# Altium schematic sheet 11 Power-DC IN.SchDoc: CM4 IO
size 420 x 297 mm; Page Create Date: March  8, 1995; Page Number: 11; Page Size: A3; Comment: radxa_1010; Page Count: 19; RevCode: V1.10; Doc: 11 Power-DC IN; DsnPath: D:\WMS\黄工\[RC126]CM4_IO_V1.10\[RC126]_V1.10\CM4 IO_V1.10.DSN; SchematicName: CM4 IO V1.10; PageName: 11 Power-DC IN; PageSize: A3; TopSchematic: True
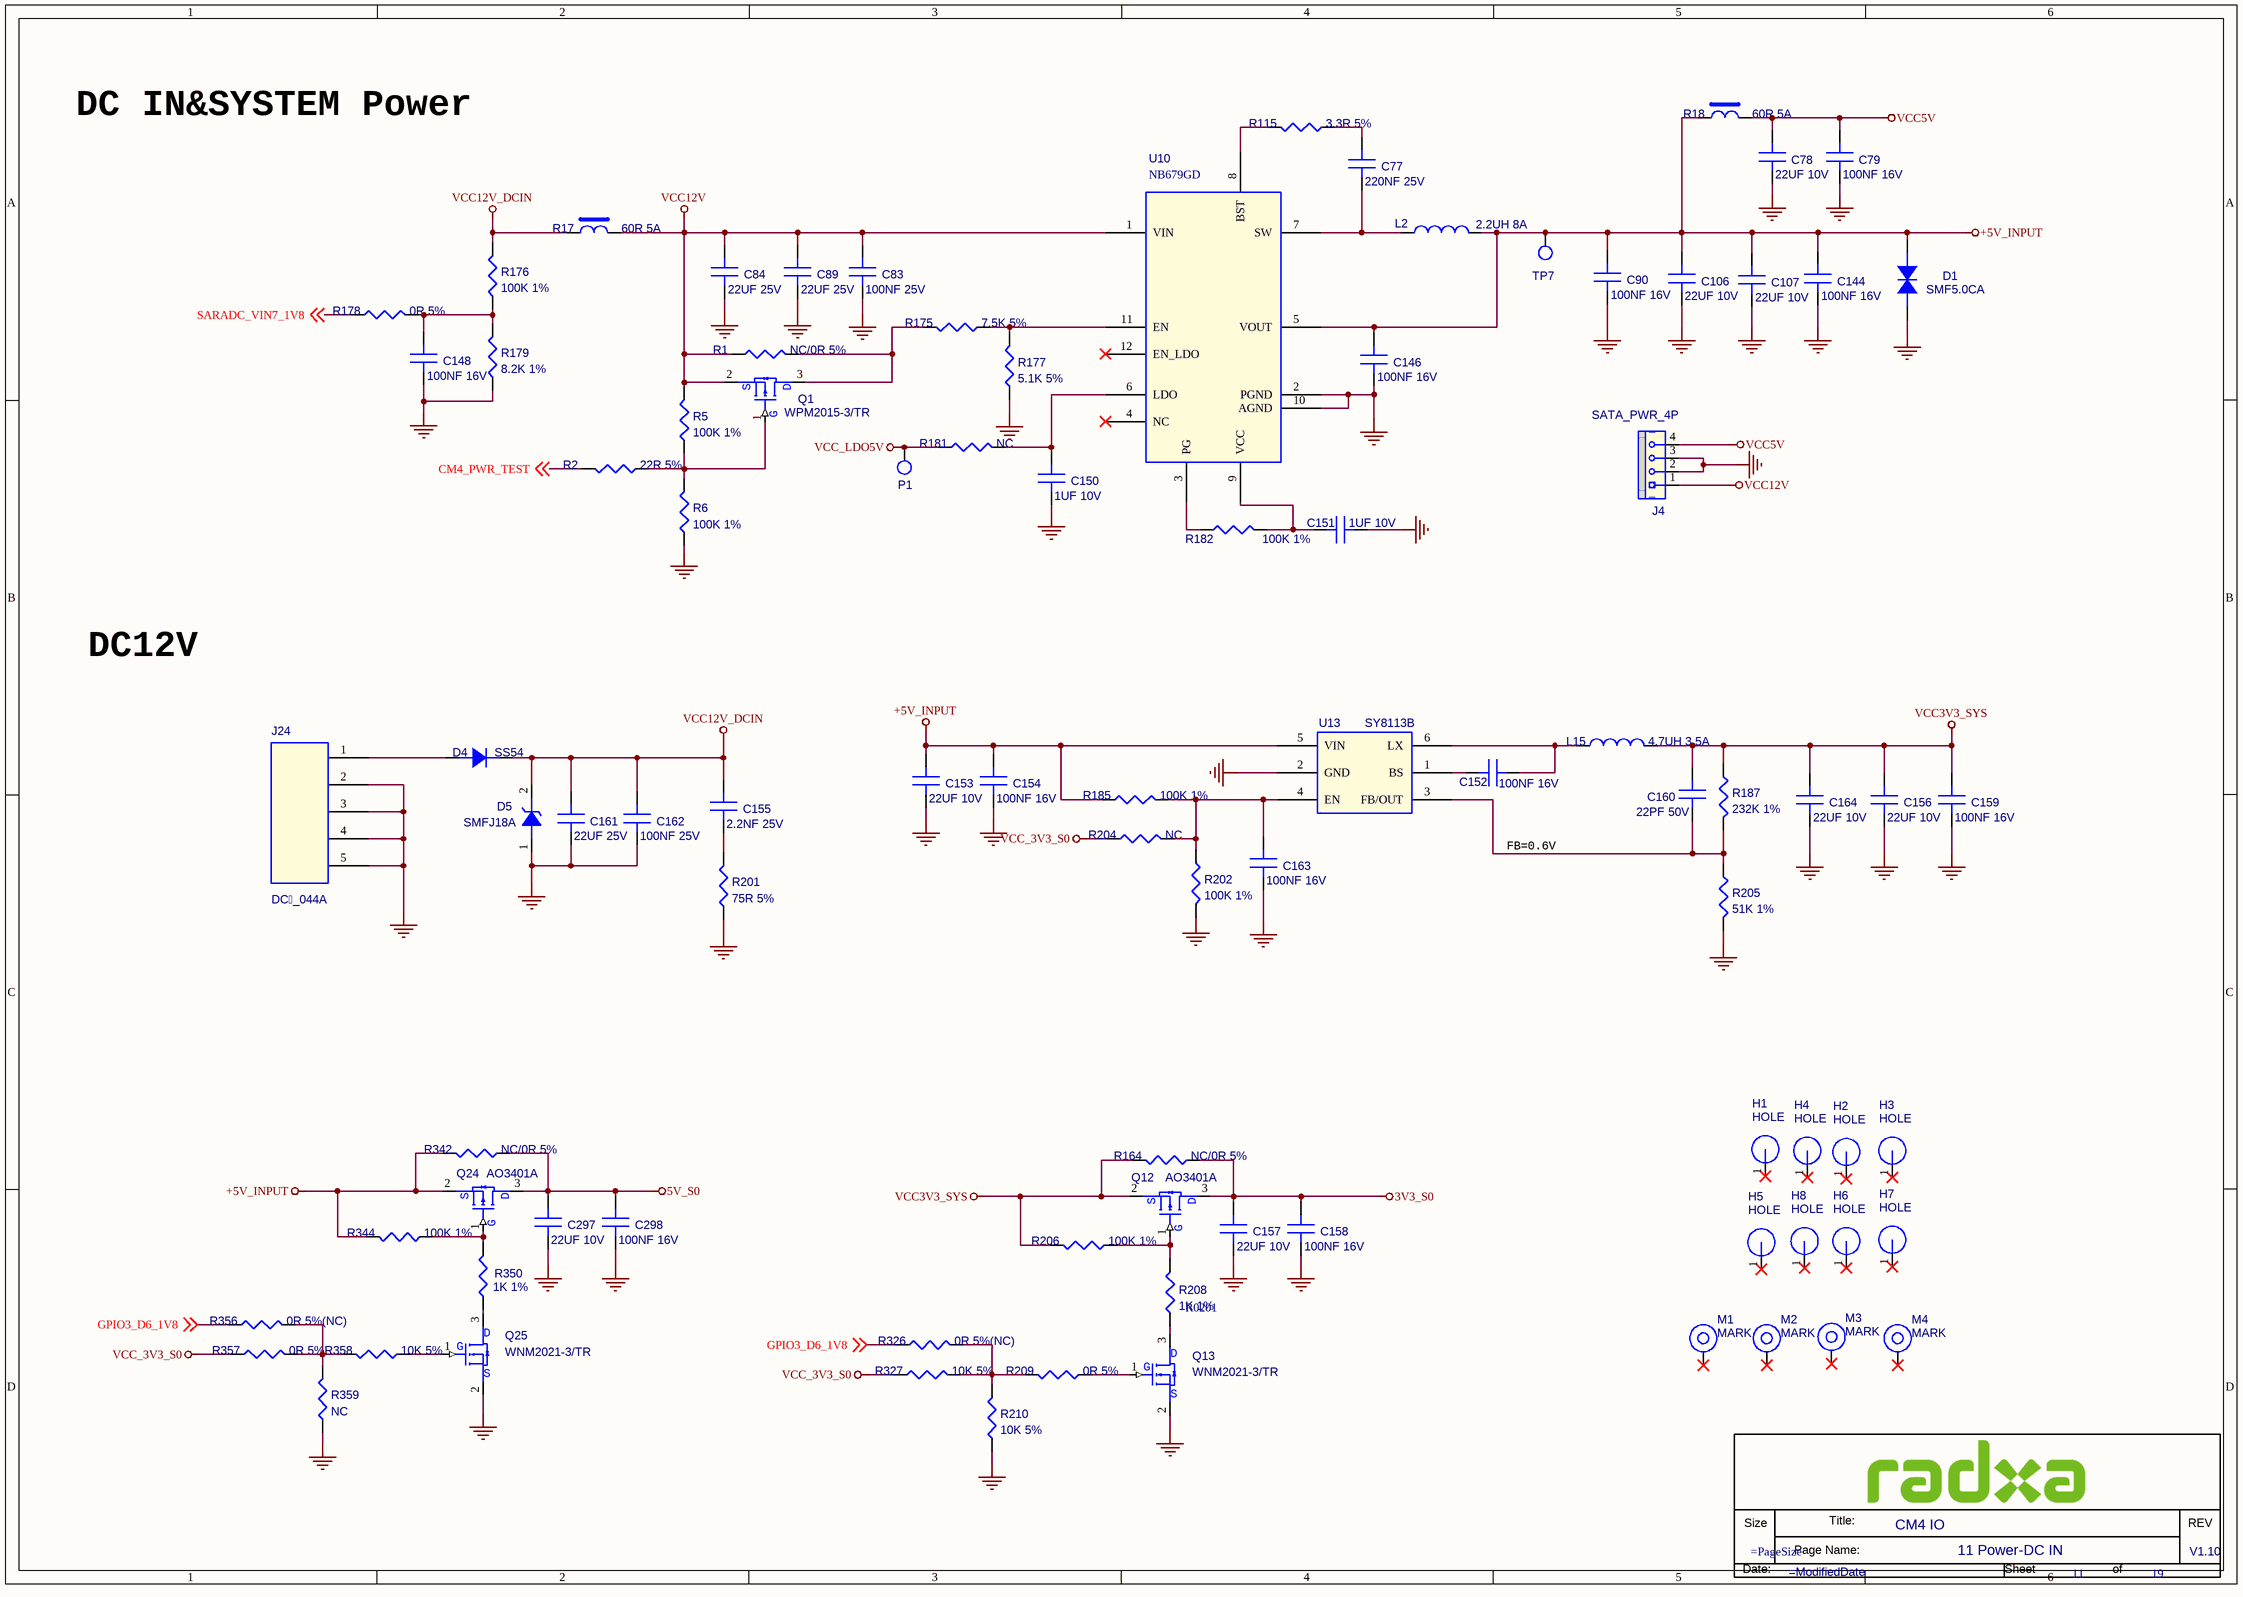
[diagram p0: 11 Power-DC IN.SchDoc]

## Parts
*  Doc: 11 Power-DC IN  RevCode: V1.10  Title: CM4 IO  Page Number: 11  Page Count: 19  (hidden comment: radxa_1010)  (graphical)
C77  220NF 25V  [C0201]
C78  22UF 10V  [C0603]
C79  100NF 16V  [C0201]
C83  100NF 25V  [C0201]
C84  22UF 25V  [C0805]
C89  22UF 25V  [C0805]
C90  100NF 16V  [C0201]
C106  22UF 10V  [C0603]
C107  22UF 10V  [C0603]
C144  100NF 16V  [C0201]
C146  100NF 16V  [C0201]
C148  100NF 16V  [C0201]
C150  1UF 10V  [C0201]
C151  1UF 10V  [C0201]
C152  100NF 16V  [C0201]
C153  22UF 10V  [C0603]
C154  100NF 16V  [C0201]
C155  2.2NF 25V  [C0201]
C156  22UF 10V  [C0603]
C157  22UF 10V  [C0603]
C158  100NF 16V  [C0201]
C159  100NF 16V  [C0201]
C160  22PF 50V  [C0201]
C161  22UF 25V  [C0805]
C162  100NF 25V  [C0201]
C163  100NF 16V  [C0201]
C164  22UF 10V  [C0603]
C297  22UF 10V  [C0603]
C298  100NF 16V  [C0201]
D1  SMF5.0CA  [SOD_123]
D4  SS54  [DO_214AC]
D5  SMFJ18A  [SOD_123]
H1  HOLE  [H3.8MM]
H2  HOLE  [H3.8MM]
H3  HOLE  [H3.8MM]
H4  HOLE  [H3.8MM]
H5  HOLE  [H3.8MM]
H6  HOLE  [H3.8MM]
H7  HOLE  [H3.8MM]
H8  HOLE  [H3.8MM]
J4  SATA_PWR_4P  [CON_TH1X4_2D54_SATA]
J24  DC_044A  [DC_TH5_12X10]
L2  2.2UH 8A  [L_6050]
L15  4.7UH 3.5A  [L_5020]
M1  MARK  [MARK]
M2  MARK  [MARK]
M3  MARK  [MARK]
M4  MARK  [MARK]
P1  TEST  [TEST]  (value not drawn)
Q1  WPM2015-3/TR  [SOT_23]
Q12  AO3401A  [SOT_23]
Q13  WNM2021-3/TR  [SOT_323]
Q24  AO3401A  [SOT_23]
Q25  WNM2021-3/TR  [SOT_323]
R1  NC/0R 5%  [R0402]
R2  22R 5%  [R0402]
R5  100K 1%  [R0402]
R6  100K 1%  [R0402]
R17  60R 5A  [FB1206]
R18  60R 5A  [FB1206]
R115  3.3R 5%  [R0402]
R164  NC/0R 5%  [R0402]
R175  7.5K 5%  [R0402]
R176  100K 1%  [R0402]
R177  5.1K 5%  [R0402]
R178  0R 5%  [R0402]
R179  8.2K 1%  [R0402]
R181  NC  [R0402]
R182  100K 1%  [R0402]
R185  100K 1%  [R0402]
R187  232K 1%  [R0402]
R201  75R 5%  [R0402]
R202  100K 1%  [R0402]
R204  NC  [R0402]
R205  51K 1%  [R0402]
R206  100K 1%  [R0402]
R208  1K 1%  PCB Footprint: R0201  [R0402]
R209  0R 5%  [R0402]
R210  10K 5%  [R0402]
R326  0R 5%(NC)  [R0402]
R327  10K 5%  [R0402]
R342  NC/0R 5%  [R0402]
R344  100K 1%  [R0402]
R350  1K 1%  [R0402]
R356  0R 5%(NC)  [R0402]
R357  0R 5%  [R0402]
R358  10K 5%  [R0402]
R359  NC  [R0402]
TP7  TP_0.7  [TEST]  (value not drawn)
U10  NB679GD  [QFN12_0D5_2]
U13  SY8113B  [SOT23_6]

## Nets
3V3_S0: C157.1(A) C158.1(A) Q12.3(D) R164.1
5V_S0: C297.1(A) C298.1(A) Q24.3(D) R342.1
+5V_INPUT: C90.1(A) C106.1(A) C107.1(A) C144.1(A) C146.1(A) C153.1(A) C154.1(A) D1.2(CATHODE) L2.2 Q24.2(S) R18.1 R185.1 R342.2 R344.2 TP7.1 U10.5(VOUT) U13.5(VIN)
GND: C78.2(B) C79.2(B) C83.2(B) C84.2(B) C89.2(B) C90.2(B) C106.2(B) C107.2(B) C144.2(B) C146.2(B) C148.2(B) C150.2(B) C151.2(B) C153.2(B) C154.2(B) C156.2(B) C157.2(B) C158.2(B) C159.2(B) C161.1(A) C162.2(B) C163.2(B) C164.2(B) C297.2(B) C298.2(B) D1.1(ANODE) D5.1(ANODE) J4.2 J4.3 J24.2 J24.3 J24.4 J24.5 Q13.2(S) Q25.2(S) R6.1 R177.1 R179.1 R201.1 R202.2 R205.2 R210.2 R359.2 U10.2(PGND) U10.10(AGND) U13.2(GND)
VCC3V3_SYS: C156.1(A) C159.1(A) C160.1(A) C164.1(A) L15.2 Q12.2(S) R164.2 R187.1 R206.2
VCC5V: C78.1(A) C79.1(A) J4.4 R18.2
VCC12V: C83.1(A) C84.1(A) C89.1(A) J4.1 Q1.2(S) R1.1 R5.2 R17.2 U10.1(VIN)
VCC12V_DCIN: C155.1(A) C161.2(B) C162.1(A) D4.2(K) D5.2(CATHODE) R17.1 R176.2
VCC_3V3_S0: R204.1 R327.1 R357.1
VCC_LDO5V: P1.1 R181.1
CM4_PWR_TEST: R2.1 ; off-sheet CM4_PWR_TEST
GPIO3_D6_1V8: R326.1 R356.1 ; off-sheet GPIO3_D6_1V8
SARADC_VIN7_1V8: R178.1 ; off-sheet SARADC_VIN7_1V8
NetC77_1: C77.1(A) R115.2
NetC77_2: C77.2(B) L2.1 U10.7(SW)
NetC148_1: C148.1(A) R176.1 R178.2 R179.2
NetC150_1: C150.1(A) R181.2 U10.6(LDO)
NetC151_1: C151.1(A) R182.2 U10.9(VCC)
NetC152_1: C152.1(A) U13.1(BS)
NetC152_2: C152.2(B) L15.1 U13.6(LX)
NetC155_2: C155.2(B) R201.2
NetC160_2: C160.2(B) R187.2 R205.1 U13.3(FB/OUT)
NetC163_1: C163.1(A) R185.2 R202.1 R204.2 U13.4(EN)
NetD4_1: D4.1(A) J24.1
NetQ1_1: Q1.1(G) R2.2 R5.1 R6.2
NetQ1_3: Q1.3(D) R1.2 R175.2
NetQ12_1: Q12.1(G) R206.1 R208.1
NetQ13_1: Q13.1(G) R209.1
NetQ13_3: Q13.3(D) R208.2
NetQ24_1: Q24.1(G) R344.1 R350.1
NetQ25_1: Q25.1(G) R358.1
NetQ25_3: Q25.3(D) R350.2
NetR115_1: R115.1 U10.8(BST)
NetR175_1: R175.1 R177.2 U10.11(EN)
NetR182_1: R182.1 U10.3(PG)
NetR209_2: R209.2 R210.1 R326.2 R327.2
NetR356_2: R356.2 R357.2 R358.2 R359.1

Not connected (* = marked no-connect by the designer): H1 1*; H2 1*; H3 1*; H4 1*; H5 1*; H6 1*; H7 1*; H8 1*; M1 1*; M2 1*; M3 1*; M4 1*; U10 4(NC)* 12(EN_LDO)*

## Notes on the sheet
- DC IN&SYSTEM Power
- DC12V
- FB=0.6V

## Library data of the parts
C77 = C: SMD  0201  220NF  25V  X5R  ±10%  ROHS; PARTS: 1; Part Reference: C77; Part Number: A1C01.00365; OriginalSymbolOrigin: (0,30); PKG_TYPE: CAP2-100-250; LEVEL: STD; PINSWAP: (A,B); Preferred: 6715f349cd0bc5
C78 = C: SMD  0603  22UF  10V  X5R  ±20%  ROHS; PARTS: 1; Part Reference: C78; Part Number: A1C01.00015; OriginalSymbolOrigin: (0,30); PKG_TYPE: CAP2-100-250; LEVEL: STD; PINSWAP: (A,B); Preferred: 6715f349cd0bc5
C79 = C: SMD  0201  100NF  16V  X5R  ±20%  ROHS; PARTS: 1; Part Reference: C79; Part Number: A1C01.00099; OriginalSymbolOrigin: (0,30); PKG_TYPE: CAP2-100-250; LEVEL: STD; PINSWAP: (A,B); Preferred: 6715f349cd0bc5
C83 = C: SMD  0201  100NF  25V  X5R  ±20%  ROHS; PARTS: 1; Part Reference: C83; Part Number: A1C01.00101; OriginalSymbolOrigin: (0,30); PKG_TYPE: CAP2-100-250; LEVEL: STD; PINSWAP: (A,B); Preferred: 6715f349cd0bc5
C84 = C: SMD  0805  22UF  25V  X5R  ±20%  ROHS; PARTS: 1; Part Reference: C84; Part Number: A1C01.00249; OriginalSymbolOrigin: (0,30); PKG_TYPE: CAP2-100-250; LEVEL: STD; PINSWAP: (A,B); Preferred: 6715f349cd0bc5
C89 = C: SMD  0805  22UF  25V  X5R  ±20%  ROHS; PARTS: 1; Part Reference: C89; Part Number: A1C01.00249; OriginalSymbolOrigin: (0,30); PKG_TYPE: CAP2-100-250; LEVEL: STD; PINSWAP: (A,B); Preferred: 6715f349cd0bc5
C90 = C: SMD  0201  100NF  16V  X5R  ±20%  ROHS; PARTS: 1; Part Reference: C90; Part Number: A1C01.00099; OriginalSymbolOrigin: (0,30); PKG_TYPE: CAP2-100-250; LEVEL: STD; PINSWAP: (A,B); Preferred: 6715f349cd0bc5
C106 = C: SMD  0603  22UF  10V  X5R  ±20%  ROHS; PARTS: 1; Part Reference: C106; Part Number: A1C01.00015; OriginalSymbolOrigin: (0,30); PKG_TYPE: CAP2-100-250; LEVEL: STD; PINSWAP: (A,B); Preferred: 6715f349cd0bc5
C107 = C: SMD  0603  22UF  10V  X5R  ±20%  ROHS; PARTS: 1; Part Reference: C107; Part Number: A1C01.00015; OriginalSymbolOrigin: (0,30); PKG_TYPE: CAP2-100-250; LEVEL: STD; PINSWAP: (A,B); Preferred: 6715f349cd0bc5
C144 = C: SMD  0201  100NF  16V  X5R  ±20%  ROHS; PARTS: 1; Part Reference: C144; Part Number: A1C01.00099; OriginalSymbolOrigin: (0,30); PKG_TYPE: CAP2-100-250; LEVEL: STD; PINSWAP: (A,B); Preferred: 6715f349cd0bc5
C146 = C: SMD  0201  100NF  16V  X5R  ±20%  ROHS; PARTS: 1; Part Reference: C146; Part Number: A1C01.00099; OriginalSymbolOrigin: (0,30); PKG_TYPE: CAP2-100-250; LEVEL: STD; PINSWAP: (A,B); Preferred: 6715f349cd0bc5
C148 = C: SMD  0201  100NF  16V  X5R  ±20%  ROHS; PARTS: 1; Part Reference: C148; Part Number: A1C01.00099; OriginalSymbolOrigin: (0,30); PKG_TYPE: CAP2-100-250; LEVEL: STD; PINSWAP: (A,B); Preferred: 6715f349cd0bc5
C150 = C: SMD  0201  1UF  10V  X5R  ±20%  ROHS; PARTS: 1; Part Reference: C150; Part Number: A1C01.00081; OriginalSymbolOrigin: (0,30); PKG_TYPE: CAP2-100-250; LEVEL: STD; PINSWAP: (A,B); Preferred: 6715f349cd0bc5
C151 = C: SMD  0201  1UF  10V  X5R  ±20%  ROHS; PARTS: 1; Part Reference: C151; Part Number: A1C01.00081; OriginalSymbolOrigin: (0,30); PKG_TYPE: CAP2-100-250; LEVEL: STD; PINSWAP: (A,B); Preferred: 6715f349cd0bc5
C152 = C: SMD  0201  100NF  16V  X5R  ±20%  ROHS; PARTS: 1; Part Reference: C152; Part Number: A1C01.00099; OriginalSymbolOrigin: (0,30); PKG_TYPE: CAP2-100-250; LEVEL: STD; PINSWAP: (A,B); Preferred: 6715f349cd0bc5
C153 = C: SMD  0603  22UF  10V  X5R  ±20%  ROHS; PARTS: 1; Part Reference: C153; Part Number: A1C01.00015; OriginalSymbolOrigin: (0,30); PKG_TYPE: CAP2-100-250; LEVEL: STD; PINSWAP: (A,B); Preferred: 6715f349cd0bc5
C154 = C: SMD  0201  100NF  16V  X5R  ±20%  ROHS; PARTS: 1; Part Reference: C154; Part Number: A1C01.00099; OriginalSymbolOrigin: (0,30); PKG_TYPE: CAP2-100-250; LEVEL: STD; PINSWAP: (A,B); Preferred: 6715f349cd0bc5
C155 = C: SMD  0201  2.2NF  25V  X7R  ±10%  ROHS; PARTS: 1; Part Reference: C155; Part Number: A1C01.00123; OriginalSymbolOrigin: (0,30); PKG_TYPE: CAP2-100-250; LEVEL: STD; PINSWAP: (A,B); Preferred: 6715f349cd0bc5
C156 = C: SMD  0603  22UF  10V  X5R  ±20%  ROHS; PARTS: 1; Part Reference: C156; Part Number: A1C01.00015; OriginalSymbolOrigin: (0,30); PKG_TYPE: CAP2-100-250; LEVEL: STD; PINSWAP: (A,B); Preferred: 6715f349cd0bc5
C157 = C: SMD  0603  22UF  10V  X5R  ±20%  ROHS; PARTS: 1; Part Reference: C157; Part Number: A1C01.00015; OriginalSymbolOrigin: (0,30); PKG_TYPE: CAP2-100-250; LEVEL: STD; PINSWAP: (A,B); Preferred: 6715f349cd0bc5
C158 = C: SMD  0201  100NF  16V  X5R  ±20%  ROHS; PARTS: 1; Part Reference: C158; Part Number: A1C01.00099; OriginalSymbolOrigin: (0,30); PKG_TYPE: CAP2-100-250; LEVEL: STD; PINSWAP: (A,B); Preferred: 6715f349cd0bc5
C159 = C: SMD  0201  100NF  16V  X5R  ±20%  ROHS; PARTS: 1; Part Reference: C159; Part Number: A1C01.00099; OriginalSymbolOrigin: (0,30); PKG_TYPE: CAP2-100-250; LEVEL: STD; PINSWAP: (A,B); Preferred: 6715f349cd0bc5
C160 = C: SMD  0201  22PF  50V  NPO  ±5%  ROHS; PARTS: 1; Part Reference: C160; Part Number: A1C01.00021; OriginalSymbolOrigin: (0,30); PKG_TYPE: CAP2-100-250; LEVEL: STD; PINSWAP: (A,B); Preferred: 6715f349cd0bc5
C161 = C: SMD  0805  22UF  25V  X5R  ±20%  ROHS; PARTS: 1; Part Reference: C161; Part Number: A1C01.00249; OriginalSymbolOrigin: (0,30); PKG_TYPE: CAP2-100-250; LEVEL: STD; PINSWAP: (A,B); Preferred: 6715f349cd0bc5
C162 = C: SMD  0201  100NF  25V  X5R  ±20%  ROHS; PARTS: 1; Part Reference: C162; Part Number: A1C01.00101; OriginalSymbolOrigin: (0,30); PKG_TYPE: CAP2-100-250; LEVEL: STD; PINSWAP: (A,B); Preferred: 6715f349cd0bc5
C163 = C: SMD  0201  100NF  16V  X5R  ±20%  ROHS; PARTS: 1; Part Reference: C163; Part Number: A1C01.00099; OriginalSymbolOrigin: (0,30); PKG_TYPE: CAP2-100-250; LEVEL: STD; PINSWAP: (A,B); Preferred: 6715f349cd0bc5
C164 = C: SMD  0603  22UF  10V  X5R  ±20%  ROHS; PARTS: 1; Part Reference: C164; Part Number: A1C01.00015; OriginalSymbolOrigin: (0,30); PKG_TYPE: CAP2-100-250; LEVEL: STD; PINSWAP: (A,B); Preferred: 6715f349cd0bc5
C297 = C: SMD  0603  22UF  10V  X5R  ±20%  ROHS; PARTS: 1; Part Reference: C297; Part Number: A1C01.00015; OriginalSymbolOrigin: (0,30); PKG_TYPE: CAP2-100-250; LEVEL: STD; PINSWAP: (A,B); Preferred: 6715f349cd0bc5
C298 = C: SMD  0201  100NF  16V  X5R  ±20%  ROHS; PARTS: 1; Part Reference: C298; Part Number: A1C01.00099; OriginalSymbolOrigin: (0,30); PKG_TYPE: CAP2-100-250; LEVEL: STD; PINSWAP: (A,B); Preferred: 6715f349cd0bc5
D1 = DIODE_S: SMD  SOD-123FL  SMF5.0CA  晶导微  ROHS; Part Reference: D1; Part Number: A1D02.00132; Temp Coeff: -55℃ to +150℃
D4 = DIODE: SMD  编带  DO-214AC  SS54  晶导微  ROHS; Part Reference: D4; Manufacturer PN: SS32; Manufacturer: 星海; Part Number: A1D02.00006; Priority: A; ROOM: CHG
D5 = TVS: SMD  编带  SOD-123  SMFJ18A  晶导微电子  ROHS; Part Reference: D5; Part Number: A1D02.00007; Preferred: 6715f349cd0bc5; Temp Coeff: -55℃ to +150℃
H1 = HOLE: 直径3.5mm hole; Part Reference: H1; PCB Footprint: HOLE_R6_2D7MM; RK PN: HOLE_3R50; Priority: A
H2 = HOLE: 直径3.5mm hole; Part Reference: H2; PCB Footprint: HOLE_R6_2D7MM; Priority: A; RK PN: HOLE_3R50
H3 = HOLE: 直径3.5mm hole; Part Reference: H3; PCB Footprint: HOLE_R6_2D7MM; Priority: A; RK PN: HOLE_3R50
H4 = HOLE: 直径3.5mm hole; Part Reference: H4; PCB Footprint: HOLE_R6_2D7MM; Priority: A; RK PN: HOLE_3R50
H5 = HOLE: 直径3.5mm hole; Part Reference: H5; PCB Footprint: HOLE_R6_2D7MM; RK PN: HOLE_3R50; Priority: A
H6 = HOLE: 直径3.5mm hole; Part Reference: H6; PCB Footprint: HOLE_R6_2D7MM; RK PN: HOLE_3R50; Priority: A
H7 = HOLE: 直径3.5mm hole; Part Reference: H7; PCB Footprint: HOLE_R6_2D7MM; Priority: A; RK PN: HOLE_3R50
H8 = HOLE: 直径3.5mm hole; Part Reference: H8; PCB Footprint: HOLE_R6_2D7MM; Priority: A; RK PN: HOLE_3R50
J4 = SATA_PWR_4P: DIP  排针座  1*4PIN  180度  无定位柱  2.54mm脚距  针长一端8.3mm  另一端3.5mm  小4PIN  白色  M2545V-4P  兴飞  ROHS; Part Reference: J4; Part Number: A1J01.00014
J24 = DC_044A_5520: DIP  5PIN  DS-044BS  内孔Φ6mm  铁芯Φ2.0mm  11.6*10.2*7.3mm  协佳  ROHS; Part Reference: J24; Part Number: A1J11.00007; Temp Coeff: NA; Preferred: 6715f352cd0bcd
L2 = L: SMD  带屏蔽  7.2x6.6x5mm  2.2UH  8A  ±20%  RXWSHC0650-2R2M  仁芯微  ROHS; Part Reference: L2; Part Number: A1L01.00163; Preferred: 6715f349cd0bc5; Temp Coeff: -55℃ to +125℃
L15 = L: SMD  带屏蔽  5.4*5.2*1.8mm  4.7UH  3.5A  ±20%  RXWSHC0520-4R7M  仁芯微  ROHS; Part Reference: L15; Part Number: A1L01.00071; Preferred: 6715f349cd0bc5; Temp Coeff: -55℃ to +125℃
M1 = MARK: MARK Symble; Part Reference: M1; Priority: A; RK PN: MARK01
M2 = MARK: MARK Symble; Part Reference: M2; Priority: A; RK PN: MARK01
M3 = MARK: MARK Symble; Part Reference: M3; RK PN: MARK01; Priority: A
M4 = MARK: MARK Symble; Part Reference: M4; RK PN: MARK01; Priority: A
P1 = TESTPOINT1: Part Reference: P1; PCB Footprint: TP_0R70
Q1 = MOSFET_PNP: SMD编带  SOT-23  WPM2015-3/TR  P沟道  ROHS; Part Reference: Q1; Part Number: A1D01.00019; Temp Coeff: -55℃ to ＋150℃
Q12 = MOSFET_PNP: SMD  编带  SOT23-3  AO3401A  P沟道  AOS  ROHS; Part Reference: Q12; Part Number: A1D01.00034; Temp Coeff: -55℃ to ＋150℃
Q13 = MOSFET_NPN: SMD编带  SOT-323  WILLSEMI(韦尔)  WNM2021-3/TR  N沟道  ROHS; Part Reference: Q13; Part Number: A1D01.00008; Temp Coeff: -55℃ to ＋150℃
Q24 = MOSFET_PNP: SMD  编带  SOT23-3  AO3401A  P沟道  AOS  ROHS; Part Reference: Q24; Part Number: A1D01.00034; Temp Coeff: -55℃ to ＋150℃
Q25 = MOSFET_NPN: SMD编带  SOT-323  WILLSEMI(韦尔)  WNM2021-3/TR  N沟道  ROHS; Part Reference: Q25; Part Number: A1D01.00008; Temp Coeff: -55℃ to ＋150℃
R1 = R: SMD  0201  0R  1/20W  ±5%  ROHS; Part Reference: R1; Part Number: A1R01.00027; PCB Footprint: R0201; Temp Coeff: -55℃ to +125℃; Preferred: 6715f349cd0bc5
R2 = R: SMD  0201  22R  1/20W  ±5%  ROHS; Part Reference: R2; Part Number: A1R01.00024; PCB Footprint: R0201; Preferred: 6715f349cd0bc5; Temp Coeff: -55℃ to +125℃
R5 = R: SMD  0201  100K  1/20W  ±1%  ROHS; Part Reference: R5; Part Number: A1R01.00165; PCB Footprint: R0201; Preferred: 6715f349cd0bc5
R6 = R: SMD  0201  100K  1/20W  ±1%  ROHS; Part Reference: R6; Part Number: A1R01.00165; PCB Footprint: R0201; Preferred: 6715f349cd0bc5
R17 = BEAD: SMD  1206  FB60R  5A  ±25%  ROHS; Part Reference: R17; Part Number: A1L09.00006; Preferred: 6715f352cd0bcd; Temp Coeff: -40℃ to +105℃
R18 = BEAD: SMD  1206  FB60R  5A  ±25%  ROHS; Part Reference: R18; Part Number: A1L09.00006; Preferred: 6715f352cd0bcd; Temp Coeff: -40℃ to +105℃
R115 = R: SMD  0201  3.3R  1/20W  ±5%  ROHS; Part Reference: R115; Part Number: A1R01.00145; PCB Footprint: R0201; Preferred: 6715f349cd0bc5; Temp Coeff: -55℃ to +125℃
R164 = R: SMD  0402  0R  1/16W  ±5%  ROHS; Part Reference: R164; Part Number: A1R01.00030; Temp Coeff: -55℃ to +155℃; Preferred: 6715f349cd0bc5
R175 = R: SMD  0201  7.5K  1/20W  ±5%  ROHS; Part Reference: R175; Part Number: A1R01.00495; PCB Footprint: R0201; Temp Coeff: -55℃ to +125℃; Preferred: 6715f349cd0bc5
R176 = R: SMD  0201  100K  1/20W  ±1%  ROHS; Part Reference: R176; Part Number: A1R01.00165; Preferred: 6715f349cd0bc5
R177 = R: SMD  0201  5.1K  1/20W  ±5%  ROHS; Part Reference: R177; Part Number: A1R01.00013; PCB Footprint: R0201; Temp Coeff: -55℃ to +125℃; Preferred: 6715f349cd0bc5
R178 = R: SMD  0201  0R  1/20W  ±5%  ROHS; Part Reference: R178; Part Number: A1R01.00027; PCB Footprint: R0201; Temp Coeff: -55℃ to +125℃; Preferred: 6715f349cd0bc5
R179 = R: SMD  0201  8.2K  1/20W  ±1%  ROHS; Part Reference: R179; Part Number: A1R01.00086; PCB Footprint: R0201; Preferred: 6715f349cd0bc5; Temp Coeff: -55℃ to +125℃
R181 = R: SMD  0201  0R  1/20W  ±5%  ROHS; Part Reference: R181; Part Number: A1R01.00027; PCB Footprint: R0201; Preferred: 6715f349cd0bc5; Temp Coeff: -55℃ to +125℃
R182 = R: SMD  0201  100K  1/20W  ±1%  ROHS; Part Reference: R182; Part Number: A1R01.00165; PCB Footprint: R0201; Preferred: 6715f349cd0bc5
R185 = R: SMD  0201  100K  1/20W  ±1%  ROHS; Part Reference: R185; Part Number: A1R01.00165; PCB Footprint: R0201; Preferred: 6715f349cd0bc5
R187 = R: SMD  0201  232K  1/20W  ±1%  ROHS; Part Reference: R187; Part Number: A1R01.00189; PCB Footprint: R0201; Preferred: 6715f349cd0bc5; Temp Coeff: -55℃ to +125℃
R201 = R: SMD  0201  75R  1/20W  ±5%  ROHS; Part Reference: R201; Part Number: A1R01.00395; PCB Footprint: R0201; Temp Coeff: -55℃ to +125℃; Preferred: 6715f349cd0bc5
R202 = R: SMD  0201  100K  1/20W  ±1%  ROHS; Part Reference: R202; Part Number: A1R01.00165; PCB Footprint: R0201; Preferred: 6715f349cd0bc5
R204 = R: SMD  0201  10K  1/20W  ±5%  ROHS; Part Reference: R204; Part Number: A1R01.00012; PCB Footprint: R0201; Preferred: 6715f349cd0bc5; Temp Coeff: -55℃ to +125℃
R205 = R: SMD  0201  51K  1/20W  ±1%  ROHS; Part Reference: R205; Part Number: A1R01.00149; PCB Footprint: R0201; Preferred: 6715f349cd0bc5; Temp Coeff: -55℃ to +125℃
R206 = R: SMD  0201  100K  1/20W  ±1%  ROHS; Part Reference: R206; Part Number: A1R01.00165; PCB Footprint: R0201; Preferred: 6715f349cd0bc5
R208 = R: SMD  0201  1K  1/20W  ±1%  ROHS; Part Reference: R208; Part Number: A1R01.00111; Preferred: 6715f349cd0bc5
R209 = R: SMD  0201  10K  1/20W  ±5%  ROHS; Part Reference: R209; Part Number: A1R01.00012; PCB Footprint: R0201; Preferred: 6715f349cd0bc5; Temp Coeff: -55℃ to +125℃
R210 = R: SMD  0201  10K  1/20W  ±5%  ROHS; Part Reference: R210; Part Number: A1R01.00012; PCB Footprint: R0201; Preferred: 6715f349cd0bc5; Temp Coeff: -55℃ to +125℃
R326 = R: SMD  0201  0R  1/20W  ±5%  ROHS; Part Reference: R326; Part Number: A1R01.00027; PCB Footprint: R0201; Preferred: 6715f349cd0bc5; Temp Coeff: -55℃ to +125℃
R327 = R: SMD  0201  0R  1/20W  ±5%  ROHS; Part Reference: R327; Part Number: A1R01.00027; PCB Footprint: R0201; Temp Coeff: -55℃ to +125℃; Preferred: 6715f349cd0bc5
R342 = R: SMD  0402  0R  1/16W  ±5%  ROHS; Part Reference: R342; Part Number: A1R01.00030; Temp Coeff: -55℃ to +155℃; Preferred: 6715f349cd0bc5
R344 = R: SMD  0201  100K  1/20W  ±1%  ROHS; Part Reference: R344; Part Number: A1R01.00165; PCB Footprint: R0201; Preferred: 6715f349cd0bc5
R350 = R: SMD  0201  1K  1/20W  ±1%  ROHS; Part Reference: R350; Part Number: A1R01.00111; PCB Footprint: R0201; Preferred: 6715f349cd0bc5
R356 = R: SMD  0201  0R  1/20W  ±5%  ROHS; Part Reference: R356; Part Number: A1R01.00027; PCB Footprint: R0201; Temp Coeff: -55℃ to +125℃; Preferred: 6715f349cd0bc5
R357 = R: SMD  0201  0R  1/20W  ±5%  ROHS; Part Reference: R357; Part Number: A1R01.00027; PCB Footprint: R0201; Temp Coeff: -55℃ to +125℃; Preferred: 6715f349cd0bc5
R358 = R: SMD  0201  10K  1/20W  ±5%  ROHS; Part Reference: R358; Part Number: A1R01.00012; PCB Footprint: R0201; Temp Coeff: -55℃ to +125℃; Preferred: 6715f349cd0bc5
R359 = R: SMD  0201  10K  1/20W  ±5%  ROHS; Part Reference: R359; Part Number: A1R01.00012; PCB Footprint: R0201; Preferred: 6715f349cd0bc5; Temp Coeff: -55℃ to +125℃
TP7 = TP: Test Point 0.7mm; Part Reference: TP7; PCB Footprint: TP_0R70; Priority: A; RK PN: TESTPOINT_0R7
U10 = NB679: SMD  DCDC  NB679GD-Z  QFN12  MPS  ROHS; Part Reference: U10; Part Number: A1I01.00033; Preferred: 6715f349cd0bc5; Temp Coeff: -40°C to +125°C
U13 = SY8113B: SMD  DCDC  SY8113BADC  SOT23-6  silergy(矽力杰)  ROHS; Part Reference: U13; Part Number: A1I01.00093; Preferred: 6715f349cd0bc5; Temp Coeff: -40℃ to +85℃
